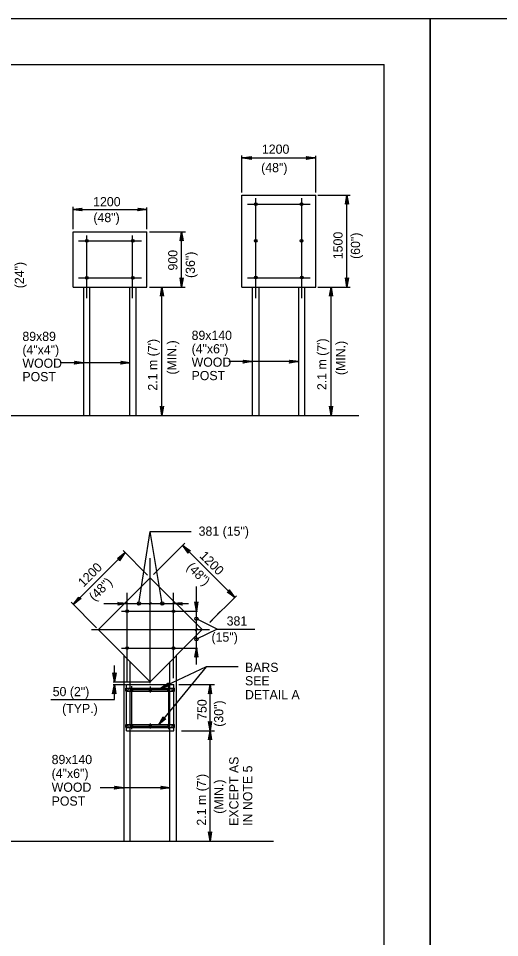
# Model space of a CAD drawing. Extents: x 649454 to 651200, y 295188 to 295782.
# Drawn here: x 650161.4 to 650317.9, y 295482.7 to 295781.6 of the extents above; entities that cross this region are included whole.
import ezdxf

# ---------------------------------------------------------------- set-up
doc = ezdxf.new("R2010")
doc.units = 0
for name, color, linetype in [('1', 7, 'Continuous'), ('2', 7, 'Continuous'), ('3', 7, 'Continuous'), ('PLT-BNDY', 7, 'Continuous')]:
    doc.layers.add(name, color=color, linetype=linetype)

msp = doc.modelspace()

# ---------------------------------------------------------------- linework, layer by layer
at = {"layer": '1'}
for p in [(649494.31, 295766.63), (650280.31, 295202.63)]:
    msp.add_line(p, (650280.31, 295766.63), dxfattribs=at)
at = {"layer": '2'}
for p, q in [((650234.06, 295725), (650234.06, 295737.04)), ((650234.06, 295736.29), (650258.06, 295736.29)), ((650258.06, 295725), (650258.06, 295736.92)), ((650234.06, 295694.25), (650234.06, 295724.12)), ((650234.06, 295724.12), (650258.06, 295724.12)), ((650238.56, 295690.62), (650238.56, 295723.12)), ((650253.56, 295690.62), (650253.56, 295723.12)), ((650258.06, 295694.25), (650258.06, 295724.12)), ((650258.81, 295724.12), (650269.22, 295724.12)), ((650268.22, 295694.25), (650268.22, 295724.12)), ((650179.19, 295713.12), (650179.19, 295720.39)), ((650179.19, 295719.51), (650203.19, 295719.51)), ((650203.19, 295713.12), (650203.19, 295720.14)), ((650235.94, 295721.25), (650256.31, 295721.25)), ((650238.56, 295721.25), (650238.56, 295721.25)), ((650253.56, 295721.25), (650253.56, 295721.25)), ((650179.19, 295694.25), (650179.19, 295712.25)), ((650179.19, 295712.25), (650203.19, 295712.25)), ((650183.69, 295690.62), (650183.69, 295711)), ((650198.56, 295690.62), (650198.56, 295711)), ((650203.19, 295694.25), (650203.19, 295712.25)), ((650204.06, 295712.25), (650215.72, 295712.25)), ((650214.47, 295694.25), (650214.47, 295712.25)), ((650180.94, 295709.25), (650201.44, 295709.25)), ((650183.69, 295709.25), (650183.69, 295709.25)), ((650198.56, 295709.25), (650198.56, 295709.25)), ((650238.56, 295709.25), (650238.56, 295709.25)), ((650253.56, 295709.25), (650253.56, 295709.25)), ((650180.94, 295697.25), (650201.44, 295697.25)), ((650183.69, 295697.25), (650183.69, 295697.25)), ((650198.56, 295697.25), (650198.56, 295697.25)), ((650235.94, 295697.25), (650256.31, 295697.25)), ((650238.56, 295697.25), (650238.56, 295697.25)), ((650253.56, 295697.25), (650253.56, 295697.25)), ((650179.19, 295694.25), (650203.19, 295694.25)), ((650182.69, 295652.5), (650182.69, 295694.25)), ((650184.69, 295652.5), (650184.69, 295694.25)), ((650197.69, 295652.5), (650197.69, 295694.25)), ((650199.69, 295652.5), (650199.69, 295694.25)), ((650204.06, 295694.25), (650215.6, 295694.25)), ((650208.06, 295652.5), (650208.06, 295694.25)), ((650234.06, 295694.25), (650258.06, 295694.25)), ((650237.56, 295652.5), (650237.56, 295694.25)), ((650239.69, 295652.5), (650239.69, 295694.25)), ((650252.56, 295652.5), (650252.56, 295694.25)), ((650254.56, 295652.5), (650254.56, 295694.25)), ((650258.81, 295694.25), (650269.22, 295694.25)), ((650263.06, 295652.5), (650263.06, 295694.25)), ((650197.69, 295669.66), (650174.94, 295669.66)), ((650252.56, 295670.04), (650229.79, 295670.04)), ((649903.44, 295652.5), (650272.04, 295652.5)), ((650200.62, 295591.36), (650204.3, 295614.74)), ((650204.3, 295614.74), (650217.56, 295614.74)), ((650215.53, 295610.97), (650205.3, 295600.74)), ((650231.7, 295593.39), (650214.83, 295610.26)), ((650179.2, 295591.09), (650196.03, 295607.79)), ((650195.49, 295608.56), (650203.43, 295600.61)), ((650204.3, 295565.49), (650204.3, 295606.11)), ((650187.43, 295582.86), (650204.3, 295599.74)), ((650221.18, 295582.86), (650204.3, 295599.74)), ((650219.27, 295571.5), (650219.27, 295596.84)), ((650196.8, 295565.86), (650196.8, 295594.86)), ((650211.8, 295567.11), (650211.8, 295594.86)), ((650232.28, 295593.85), (650223.8, 295585.37)), ((650186.8, 295583.49), (650178.54, 295591.75)), ((650189.21, 295591.36), (650204.3, 295591.36)), ((650193.18, 295591.36), (650204.3, 295591.36)), ((650203.93, 295590.99), (650204.68, 295591.74)), ((650204.3, 295591.36), (650215.43, 295591.36)), ((650204.3, 295591.36), (650216.69, 295591.36)), ((650194.93, 295588.86), (650219.68, 295588.86)), ((650195.05, 295588.86), (650219.68, 295588.86)), ((650227.05, 295588.74), (650223.61, 295585.21)), ((650226, 295583.04), (650219.27, 295586.39)), ((650185.18, 295582.86), (650223.55, 295582.86)), ((650185.18, 295582.86), (650223.55, 295582.86)), ((650204.3, 295565.86), (650187.3, 295582.86)), ((650204.3, 295565.86), (650221.18, 295582.86)), ((650218.89, 295582.49), (650219.64, 295583.24)), ((650226, 295583.04), (650219.27, 295579.72)), ((650226, 295583.04), (650238.24, 295583.04)), ((650194.93, 295576.86), (650219.68, 295576.86)), ((650195.05, 295576.86), (650219.68, 295576.86)), ((650195.8, 295514.11), (650195.8, 295574.49)), ((650212.8, 295514.11), (650212.8, 295574.49)), ((650192.66, 295565.86), (650192.66, 295571.19)), ((650197.8, 295565.49), (650197.8, 295572.36)), ((650210.68, 295565.49), (650210.68, 295572.36)), ((650192.24, 295565.86), (650203.93, 295565.86)), ((650192.27, 295564.99), (650196.18, 295564.99)), ((650192.66, 295560.12), (650192.66, 295564.99)), ((650196.55, 295549.99), (650196.55, 295564.99)), ((650196.55, 295564.99), (650211.93, 295564.99)), ((650197.8, 295550.61), (650197.8, 295565.49)), ((650198.3, 295550.49), (650198.3, 295564.49)), ((650204.31, 295562.46), (650204.31, 295564.34)), ((650210.3, 295550.49), (650210.3, 295564.49)), ((650210.68, 295550.49), (650210.68, 295565.49)), ((650211.93, 295549.99), (650211.93, 295564.99)), ((650213.55, 295564.99), (650225.21, 295564.99)), ((650223.71, 295549.99), (650223.71, 295564.99)), ((650196.3, 295562.86), (650196.3, 295563.86)), ((650196.3, 295563.86), (650197.39, 295563.86)), ((650196.3, 295562.86), (650197.39, 295562.86)), ((650197.39, 295563.86), (650211.3, 295563.86)), ((650197.39, 295562.86), (650211.3, 295562.86)), ((650198.3, 295563.36), (650210.3, 295563.36)), ((650211.3, 295563.86), (650212.18, 295563.86)), ((650211.3, 295562.86), (650212.18, 295562.86)), ((650212.18, 295562.86), (650212.18, 295563.86)), ((650171.98, 295560.12), (650192.66, 295560.12)), ((650196.3, 295550.99), (650196.3, 295551.99)), ((650196.3, 295551.99), (650197.39, 295551.99)), ((650197.39, 295551.99), (650211.14, 295551.99)), ((650204.31, 295550.71), (650204.31, 295552.37)), ((650211.14, 295551.99), (650212.18, 295551.99)), ((650212.18, 295550.99), (650212.18, 295551.99)), ((650196.3, 295550.99), (650197.39, 295550.99)), ((650196.55, 295549.99), (650211.93, 295549.99)), ((650197.39, 295550.99), (650211.14, 295550.99)), ((650197.8, 295514.11), (650197.8, 295550.49)), ((650198.3, 295551.49), (650210.3, 295551.49)), ((650210.68, 295514.11), (650210.68, 295550.49)), ((650211.14, 295550.99), (650212.18, 295550.99)), ((650214.43, 295549.99), (650225.21, 295549.99)), ((650223.71, 295514.11), (650223.71, 295549.99)), ((650210.68, 295531.44), (650187.99, 295531.44)), ((649979.81, 295514.11), (650244.3, 295514.11))]:
    msp.add_line(p, q, dxfattribs=at)
for points in [[(650237.06, 295735.92), (650236.94, 295736.17), (650234.06, 295736.29), (650237.06, 295735.92), (650237.06, 295735.79), (650234.06, 295736.29), (650236.94, 295736.29), (650237.06, 295736.54), (650234.06, 295736.29), (650237.06, 295736.67), (650237.06, 295736.54)], [(650255.19, 295736.54), (650255.19, 295736.29), (650258.06, 295736.29), (650255.19, 295736.54), (650255.06, 295736.67), (650258.06, 295736.29), (650255.19, 295736.17), (650255.19, 295735.92), (650258.06, 295736.29), (650255.06, 295735.79), (650255.19, 295735.92)], [(650267.84, 295721.37), (650268.09, 295721.5), (650268.22, 295724.12), (650267.84, 295721.37), (650267.72, 295721.25), (650268.22, 295724.12), (650268.34, 295721.5), (650268.59, 295721.37), (650268.22, 295724.12), (650268.72, 295721.25), (650268.59, 295721.37)], [(650182.06, 295719.14), (650181.94, 295719.39), (650179.19, 295719.51), (650182.06, 295719.14), (650182.19, 295719.01), (650179.19, 295719.51), (650181.94, 295719.51), (650182.06, 295719.76), (650179.19, 295719.51), (650182.19, 295719.89), (650182.06, 295719.76)], [(650200.31, 295719.76), (650200.44, 295719.64), (650203.19, 295719.51), (650200.31, 295719.76), (650200.19, 295719.89), (650203.19, 295719.51), (650200.44, 295719.39), (650200.31, 295719.26), (650203.19, 295719.51), (650200.19, 295719.01), (650200.31, 295719.26)], [(650214.1, 295709.37), (650214.35, 295709.5), (650214.47, 295712.25), (650214.1, 295709.37), (650213.97, 295709.25), (650214.47, 295712.25), (650214.6, 295709.5), (650214.85, 295709.37), (650214.47, 295712.25), (650214.97, 295709.25), (650214.85, 295709.37)], [(650214.85, 295697.12), (650214.72, 295697), (650214.47, 295694.25), (650214.85, 295697.12), (650214.97, 295697.25), (650214.47, 295694.25), (650214.35, 295697), (650214.1, 295697.12), (650214.47, 295694.25), (650213.97, 295697.25), (650214.1, 295697.12)], [(650268.59, 295697.12), (650268.34, 295697), (650268.22, 295694.25), (650268.59, 295697.12), (650268.72, 295697.25), (650268.22, 295694.25), (650268.09, 295697), (650267.84, 295697.12), (650268.22, 295694.25), (650267.72, 295697.25), (650267.84, 295697.12)], [(650207.69, 295691.5), (650207.94, 295691.62), (650208.06, 295694.25), (650207.69, 295691.5), (650207.56, 295691.25), (650208.06, 295694.25), (650208.19, 295691.62), (650208.44, 295691.5), (650208.06, 295694.25), (650208.56, 295691.25), (650208.44, 295691.5)], [(650262.69, 295691.5), (650262.94, 295691.62), (650263.06, 295694.25), (650262.69, 295691.5), (650262.56, 295691.25), (650263.06, 295694.25), (650263.19, 295691.62), (650263.44, 295691.5), (650263.06, 295694.25), (650263.56, 295691.25), (650263.44, 295691.5)], [(650179.74, 295670.03), (650179.86, 295669.91), (650182.61, 295669.66), (650179.74, 295670.03), (650179.61, 295670.16), (650182.61, 295669.66), (650179.86, 295669.53), (650179.74, 295669.41), (650182.61, 295669.66), (650179.61, 295669.16), (650179.74, 295669.41)], [(650194.81, 295670.03), (650194.94, 295669.91), (650197.69, 295669.66), (650194.81, 295670.03), (650194.69, 295670.16), (650197.69, 295669.66), (650194.94, 295669.53), (650194.81, 295669.41), (650197.69, 295669.66), (650194.69, 295669.16), (650194.81, 295669.41)], [(650234.59, 295670.41), (650234.71, 295670.29), (650237.46, 295670.04), (650234.59, 295670.41), (650234.46, 295670.54), (650237.46, 295670.04), (650234.71, 295669.91), (650234.59, 295669.79), (650237.46, 295670.04), (650234.46, 295669.54), (650234.59, 295669.79)], [(650249.69, 295670.41), (650249.81, 295670.29), (650252.56, 295670.04), (650249.69, 295670.41), (650249.56, 295670.54), (650252.56, 295670.04), (650249.81, 295669.91), (650249.69, 295669.79), (650252.56, 295670.04), (650249.56, 295669.54), (650249.69, 295669.79)], [(650208.44, 295655.25), (650208.31, 295655.12), (650208.06, 295652.5), (650208.44, 295655.25), (650208.56, 295655.5), (650208.06, 295652.5), (650207.94, 295655.12), (650207.69, 295655.25), (650208.06, 295652.5), (650207.56, 295655.5), (650207.69, 295655.25)], [(650263.44, 295655.25), (650263.19, 295655.12), (650263.06, 295652.5), (650263.44, 295655.25), (650263.56, 295655.5), (650263.06, 295652.5), (650262.94, 295655.12), (650262.69, 295655.25), (650263.06, 295652.5), (650262.56, 295655.5), (650262.69, 295655.25)], [(650208.18, 295591.36), (650204.3, 295614.74)], [(650216.58, 295608.01), (650216.7, 295608.26), (650214.83, 295610.26), (650216.58, 295608.01), (650216.58, 295607.76), (650214.83, 295610.26), (650216.83, 295608.39), (650217.08, 295608.51), (650214.83, 295610.26), (650217.33, 295608.51), (650217.08, 295608.51)], [(650193.78, 295606.04), (650193.9, 295606.04), (650196.03, 295607.79), (650193.78, 295606.04), (650193.65, 295606.04), (650196.03, 295607.79), (650194.15, 295605.79), (650194.28, 295605.54), (650196.03, 295607.79), (650194.28, 295605.29), (650194.28, 295605.54)], [(650230.08, 295595.51), (650229.95, 295595.39), (650231.7, 295593.39), (650230.08, 295595.51), (650229.95, 295595.76), (650231.7, 295593.39), (650229.7, 295595.14), (650229.58, 295595.01), (650231.7, 295593.39), (650229.33, 295595.01), (650229.58, 295595.01)], [(650181.58, 295592.96), (650181.33, 295592.96), (650179.2, 295591.09), (650181.58, 295592.96), (650181.83, 295592.96), (650179.2, 295591.09), (650181.2, 295593.09), (650181.08, 295593.34), (650179.2, 295591.09), (650181.08, 295593.46), (650181.08, 295593.34)], [(650193.92, 295591.61), (650194.04, 295591.49), (650196.79, 295591.36), (650193.92, 295591.61), (650193.79, 295591.74), (650196.79, 295591.36), (650194.04, 295591.24), (650194.04, 295591.11), (650196.79, 295591.36), (650193.79, 295590.86), (650194.04, 295591.11)], [(650214.55, 295590.99), (650214.43, 295591.24), (650211.8, 295591.36), (650214.55, 295590.99), (650214.68, 295590.86), (650211.8, 295591.36), (650214.43, 295591.36), (650214.55, 295591.61), (650211.8, 295591.36), (650214.68, 295591.74), (650214.55, 295591.61)], [(650219.64, 295591.74), (650219.39, 295591.61), (650219.27, 295588.86), (650219.64, 295591.74), (650219.77, 295591.86), (650219.27, 295588.86), (650219.02, 295591.61), (650218.89, 295591.74), (650219.27, 295588.86), (650218.77, 295591.86), (650218.89, 295591.74)], [(650218.89, 295573.99), (650219.02, 295574.11), (650219.27, 295576.86), (650218.89, 295573.99), (650218.77, 295573.86), (650219.27, 295576.86), (650219.39, 295574.11), (650219.52, 295573.99), (650219.27, 295576.86), (650219.77, 295573.86), (650219.52, 295573.99)], [(650232.91, 295570.74), (650222.43, 295570.74), (650207.05, 295551.99)], [(650222.43, 295570.74), (650207.68, 295563.86)], [(650192.91, 295568.61), (650192.79, 295568.61), (650192.66, 295565.86), (650192.91, 295568.61), (650193.16, 295568.86), (650192.66, 295565.86), (650192.41, 295568.61), (650192.29, 295568.61), (650192.66, 295565.86), (650192.16, 295568.86), (650192.29, 295568.61)], [(650192.29, 295562.24), (650192.41, 295562.24), (650192.66, 295564.99), (650192.29, 295562.24), (650192.04, 295561.99), (650192.66, 295564.99), (650192.79, 295562.24), (650192.91, 295562.24), (650192.66, 295564.99), (650193.04, 295561.99), (650192.91, 295562.24)], [(650210.3, 295564.74), (650210.25, 295564.86), (650207.68, 295563.86), (650210.3, 295564.74), (650210.62, 295564.61), (650207.68, 295563.86), (650210.09, 295565.2), (650210.04, 295565.31), (650207.68, 295563.86), (650210.22, 295565.53), (650210.04, 295565.31)], [(650223.33, 295562.11), (650223.58, 295562.24), (650223.71, 295564.99), (650223.33, 295562.11), (650223.21, 295561.99), (650223.71, 295564.99), (650223.96, 295562.24), (650224.08, 295562.11), (650223.71, 295564.99), (650224.21, 295561.99), (650224.08, 295562.11)], [(650224.08, 295552.86), (650223.96, 295552.74), (650223.71, 295549.99), (650224.08, 295552.86), (650224.21, 295552.99), (650223.71, 295549.99), (650223.58, 295552.74), (650223.46, 295552.86), (650223.71, 295549.99), (650223.21, 295552.99), (650223.46, 295552.86)], [(650223.33, 295547.24), (650223.58, 295547.24), (650223.71, 295549.99), (650223.33, 295547.24), (650223.21, 295546.99), (650223.71, 295549.99), (650223.96, 295547.24), (650224.08, 295547.24), (650223.71, 295549.99), (650224.21, 295546.99), (650224.08, 295547.24)], [(650192.79, 295531.82), (650192.92, 295531.69), (650195.67, 295531.44), (650192.79, 295531.82), (650192.67, 295531.94), (650195.67, 295531.44), (650192.92, 295531.32), (650192.79, 295531.19), (650195.67, 295531.44), (650192.67, 295530.94), (650192.79, 295531.19)], [(650207.8, 295531.82), (650207.93, 295531.69), (650210.68, 295531.44), (650207.8, 295531.82), (650207.68, 295531.94), (650210.68, 295531.44), (650207.93, 295531.32), (650207.8, 295531.19), (650210.68, 295531.44), (650207.68, 295530.94), (650207.8, 295531.19)], [(650224.08, 295516.99), (650223.96, 295516.86), (650223.71, 295514.11), (650224.08, 295516.99), (650224.21, 295517.11), (650223.71, 295514.11), (650223.58, 295516.86), (650223.46, 295516.99), (650223.71, 295514.11), (650223.21, 295517.11), (650223.46, 295516.99)]]:
    msp.add_lwpolyline(points, dxfattribs=at)
for centre, radius in [((650238.59, 295721.21), 0.441), ((650253.47, 295721.21), 0.441), ((650183.7, 295709.26), 0.441), ((650198.59, 295709.27), 0.441), ((650238.56, 295709.26), 0.441), ((650253.47, 295709.26), 0.441), ((650183.67, 295697.29), 0.441), ((650198.66, 295697.25), 0.441), ((650238.56, 295697.33), 0.441), ((650253.54, 295697.33), 0.441), ((650200.62, 295591.36), 0.55), ((650208.18, 295591.36), 0.55), ((650196.77, 295588.83), 0.441), ((650211.8, 295588.81), 0.441), ((650219.27, 295586.39), 0.55), ((650219.27, 295579.72), 0.55), ((650196.77, 295576.88), 0.441), ((650211.8, 295576.87), 0.441), ((650196.78, 295563.36), 0.35), ((650198.3, 295563.36), 0.35), ((650204.29, 295563.36), 0.35), ((650210.27, 295563.36), 0.35), ((650211.7, 295563.36), 0.35), ((650196.78, 295551.49), 0.35), ((650198.3, 295551.49), 0.35), ((650204.31, 295551.49), 0.35), ((650210.3, 295551.49), 0.35), ((650211.69, 295551.49), 0.35)]:
    msp.add_circle(centre, radius, dxfattribs=at)
at = {"layer": '3'}
for p, q in [((650196.8, 295588.86), (650196.8, 295588.86)), ((650196.93, 295588.86), (650196.93, 295588.86)), ((650211.8, 295588.86), (650211.8, 295588.86)), ((650211.8, 295588.86), (650211.8, 295588.86)), ((650196.8, 295576.86), (650196.8, 295576.86)), ((650196.93, 295576.86), (650196.93, 295576.86)), ((650211.8, 295576.86), (650211.8, 295576.86)), ((650211.8, 295576.86), (650211.8, 295576.86))]:
    msp.add_line(p, q, dxfattribs=at)
msp.add_lwpolyline([(650209.05, 295553.86), (650208.8, 295553.86), (650207.05, 295551.99), (650209.05, 295553.86), (650209.3, 295553.86), (650207.05, 295551.99), (650208.55, 295554.11), (650208.43, 295554.36), (650207.05, 295551.99), (650208.43, 295554.49), (650208.43, 295554.36)], dxfattribs=at)
at = {"layer": 'PLT-BNDY'}
for points in [[(649454.31, 295781.63), (650295.31, 295781.63), (650295.31, 295187.63), (649454.31, 295187.63)], [(650295.31, 295781.63), (651136.31, 295781.63), (651136.31, 295187.63), (650295.31, 295187.63)]]:
    msp.add_lwpolyline(points, close=True, dxfattribs=at)

# ---------------------------------------------------------------- texts
at = {"layer": '3'}
for s, height, p in [('1200', 3, (650240.58, 295737.6)), ('(48")', 3, (650240.33, 295731.6)), ('1200', 3, (650185.71, 295720.53)), ('(48")', 3, (650185.79, 295715.37)), ('89x89', 2.988, (650162.72, 295676.73)), ('89x140', 2.988, (650217.73, 295677.08)), ('(4"x4")', 2.988, (650162.72, 295672.37)), ('(4"x6")', 2.988, (650217.73, 295672.71)), ('WOOD', 2.988, (650162.72, 295668.01)), ('WOOD', 2.988, (650217.73, 295668.35)), ('POST', 2.988, (650162.72, 295663.64)), ('POST', 2.988, (650217.73, 295663.99)), ('381 (15")', 3, (650220, 295613.39)), ('381', 3, (650229.12, 295584.19)), (' (15")', 3, (650223.07, 295578.94)), ('BARS', 2.988, (650235.09, 295569.11)), ('SEE', 2.988, (650235.09, 295564.74)), ('50 (2")', 3, (650172.56, 295561.23)), ('DETAIL A', 2.988, (650235.09, 295560.24)), ('(TYP.)', 3, (650175.62, 295555.72)), ('89x140', 3, (650172.22, 295539.13)), ('(4"x6")', 3, (650172.22, 295534.63)), ('WOOD', 3, (650172.22, 295530.13)), ('POST', 3, (650172.22, 295525.63))]:
    msp.add_text(s, height=height, dxfattribs=at).set_placement(p)
for s, rotation, p in [('1500', 90, (650266.81, 295703.32)), ('(60")', 90, (650272.49, 295703.41)), ('900', 90, (650213.11, 295699.64)), ('(36")', 90, (650218.8, 295697.22)), ('(24")', 90, (650163.24, 295693.87)), ("2.1 m (7') ", 90, (650206.54, 295660.58)), ('(MIN.)', 90, (650212.78, 295665.8)), ("2.1 m (7') ", 90, (650261.57, 295660.75)), ('(MIN.)', 90, (650267.65, 295665.63)), ('1200', 315, (650220.08, 295606.63)), ('1200', 45, (650182.57, 295596.51)), ('(48")', 315, (650215.9, 295602.95)), ('(48")', 45, (650186.13, 295591.96)), ('750', 90, (650222.61, 295553.53)), ('(30")', 90, (650228.03, 295551.28)), ('EXCEPT AS', 90, (650232.96, 295519.06)), ('IN NOTE 5', 90, (650237.46, 295519.06)), ("2.1 m (7') ", 90, (650222.43, 295519.14)), ('(MIN.)', 90, (650228.08, 295522.99))]:
    msp.add_text(s, height=3, rotation=rotation, dxfattribs=at).set_placement(p)

doc.saveas('drawing.dxf')
